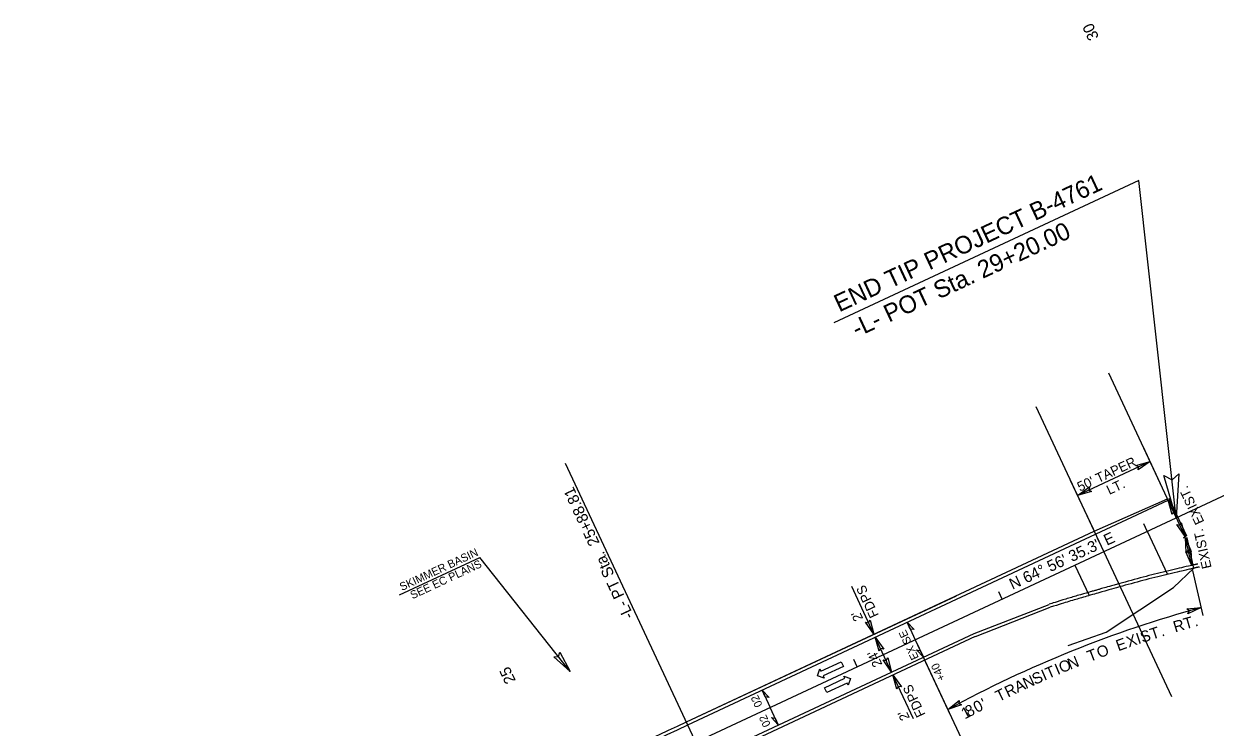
# Model space of a CAD drawing. Extents: x 2320644 to 2322941, y 921672 to 923041.
# Drawn here: x 2321799 to 2322543, y 922465 to 922904 of the extents above; entities that cross this region are included whole.
import ezdxf

# ---------------------------------------------------------------- set-up
doc = ezdxf.new("R2010")
doc.units = 0
for name, color, linetype in [('Matchline', 7, 'Continuous'), ('Matchline Text', 7, 'Continuous'), ('Prop Approach Slab', 7, 'Continuous'), ('Prop Conc Shoulder Berm Gutter', 7, 'Continuous'), ('Prop Dimension', 7, 'Continuous'), ('Prop Horizontal Alignment Station Label', 7, 'Continuous'), ('Prop Horizontal Alignment Tick Small', 7, 'Continuous'), ('Prop Lane Arrow CELL', 7, 'Continuous'), ('Prop North Arrow NAD83 for Plan Sheets CELL', 7, 'Continuous'), ('Prop Superelevation  Arrow CELL', 7, 'Continuous'), ('Prop Terminator CELL', 7, 'Continuous'), ('Sheet Profile Grid Minor CELL', 7, 'Continuous'), ('Sheet Sticker Exception Certification CELL', 7, 'Continuous'), ('Skimmer Basin Both CELL', 7, 'Continuous')]:
    doc.layers.add(name, color=color, linetype=linetype)

msp = doc.modelspace()

# ---------------------------------------------------------------- linework, layer by layer
at = {"layer": 'Matchline'}
msp.add_line((2322219.06, 922455.24), (2322939.2, 922791.92), dxfattribs=at)
at = {"layer": 'Prop Approach Slab'}
for p, q in [((2322213.98, 922466.11), (2322514, 922606.38)), ((2322392.84, 922523.24), (2322439.66, 922541.38)), ((2322224.14, 922444.37), (2322392.84, 922523.24))]:
    msp.add_line(p, q, dxfattribs=at)
msp.add_arc((2152812.15, 1284810.45), 399988, 294.9912984, 295.0568478, dxfattribs=at)
for points, degree in [([(2322528.68, 922565.7), (2322527.14, 922565.35), (2322525.6, 922565), (2322510.52, 922561.51), (2322497.08, 922558.05), (2322480.35, 922553.43), (2322476.17, 922552.25), (2322472, 922551.06), (2322470.33, 922550.58), (2322469.49, 922550.34), (2322466.99, 922549.62), (2322465.32, 922549.14), (2322456.98, 922546.73), (2322450.3, 922544.77), (2322442.33, 922542.25), (2322440.99, 922541.82), (2322439.66, 922541.39)], 3), ([(2322532.6, 922566.58), (2322531.3, 922566.29), (2322529.99, 922565.99), (2322528.68, 922565.7)], 2)]:
    msp.add_open_spline(points, degree=degree, dxfattribs=at)
at = {"layer": 'Prop Conc Shoulder Berm Gutter'}
for p, q in [((2322467.86, 922587.01), (2322513.56, 922607.34)), ((2322213.13, 922467.93), (2322467.86, 922587.01)), ((2322213.13, 922467.93), (2322381.8, 922546.78)), ((2322393.57, 922521.38), (2322440.39, 922539.52)), ((2322224.99, 922442.56), (2322393.65, 922521.41))]:
    msp.add_line(p, q, dxfattribs=at)
msp.add_arc((2152812.15, 1284810.45), 399986, 295.0427173, 295.0568478, dxfattribs=at)
for points, degree in [([(2322529.12, 922563.74), (2322528.97, 922563.71), (2322528.83, 922563.68), (2322525.7, 922562.97), (2322522.72, 922562.28), (2322516.78, 922560.87), (2322501.94, 922557.27), (2322487.21, 922553.31), (2322472.51, 922549.13), (2322469.57, 922548.28), (2322463.69, 922546.59), (2322460.75, 922545.74), (2322451.98, 922543.16), (2322446.16, 922541.4), (2322440.39, 922539.52)], 3), ([(2322533.47, 922564.72), (2322532.02, 922564.4), (2322530.57, 922564.07), (2322529.12, 922563.74)], 2)]:
    msp.add_open_spline(points, degree=degree, dxfattribs=at)
at = {"layer": 'Prop Dimension'}
msp.add_line((2322218.43, 922456.6), (2322137.68, 922629.33), dxfattribs=at)
at = {"layer": 'Prop Horizontal Alignment Station Label'}
for p, q in [((2322350.95, 922530.15), (2322356.02, 922519.27)), ((2322260.36, 922487.8), (2322265.43, 922476.92))]:
    msp.add_line(p, q, dxfattribs=at)
for points in [[(2322350.95, 922530.15), (2322355.3, 922525.56), (2322352.9, 922525.96)], [(2322361.1, 922508.4), (2322356.75, 922512.99), (2322359.15, 922512.59)], [(2322260.36, 922487.8), (2322264.71, 922483.2), (2322262.31, 922483.6)], [(2322270.51, 922466.05), (2322266.16, 922470.64), (2322268.56, 922470.24)]]:
    msp.add_lwpolyline(points, close=True, dxfattribs=at)
at = {"layer": 'Prop Horizontal Alignment Tick Small'}
for p, q in [((2322500.96, 922587.04), (2322498.84, 922591.57)), ((2322410.37, 922544.68), (2322408.26, 922549.21)), ((2322319.78, 922502.33), (2322317.67, 922506.86))]:
    msp.add_line(p, q, dxfattribs=at)
at = {"layer": 'Prop Lane Arrow CELL'}
for p, q in [((2322294.96, 922496.75), (2322296.46, 922500.99)), ((2322296.46, 922500.99), (2322297.09, 922499.63)), ((2322297.09, 922499.63), (2322309.78, 922505.54)), ((2322311.18, 922502.55), (2322298.49, 922496.64)), ((2322309.78, 922505.54), (2322311.18, 922502.55)), ((2322299.12, 922495.28), (2322294.96, 922496.75)), ((2322298.49, 922496.64), (2322299.12, 922495.28)), ((2322299.37, 922489.26), (2322312.06, 922495.18)), ((2322312.06, 922495.18), (2322311.43, 922496.54)), ((2322311.43, 922496.54), (2322315.59, 922495.06)), ((2322315.59, 922495.06), (2322314.09, 922490.83)), ((2322300.77, 922486.27), (2322299.37, 922489.26)), ((2322313.46, 922492.19), (2322300.77, 922486.27)), ((2322314.09, 922490.83), (2322313.46, 922492.19))]:
    msp.add_line(p, q, dxfattribs=at)
at = {"layer": 'Prop North Arrow NAD83 for Plan Sheets CELL'}
for p, q in [((2322495.73, 922806.14), (2322305.22, 922717.23)), ((2322519.08, 922595.51), (2322495.73, 922806.14)), ((2322513.17, 922608.16), (2322498.37, 922639.89)), ((2322502.69, 922630.61), (2322457.38, 922609.47)), ((2322467.27, 922588.26), (2322453.05, 922618.74)), ((2322524.6, 922583.69), (2322514, 922606.38)), ((2322523.48, 922583.16), (2322525.43, 922584.08)), ((2322525.77, 922583.02), (2322523.7, 922582.7)), ((2322528.68, 922565.7), (2322524.79, 922582.87)), ((2322033.95, 922547.27), (2322084.15, 922570.67)), ((2322140.55, 922499.39), (2322084.15, 922570.67)), ((2322535.77, 922534.39), (2322529.38, 922562.59)), ((2322330.24, 922522.67), (2322316.34, 922552.45)), ((2322341.23, 922499.11), (2322331.08, 922520.86)), ((2322356.02, 922519.27), (2322361.1, 922508.4)), ((2322378.24, 922471.65), (2322362.63, 922505.1)), ((2322354.9, 922469.82), (2322342.08, 922497.3))]:
    msp.add_line(p, q, dxfattribs=at)
msp.add_arc((2322726.81, 921833.68), 731.37, 105.23298, 118.62896, dxfattribs=at)
at = {"layer": 'Prop Superelevation  Arrow CELL'}
msp.add_line((2322270.51, 922466.05), (2322265.43, 922476.92), dxfattribs=at)
at = {"layer": 'Sheet Profile Grid Minor CELL'}
for p, q in [((2322514.38, 922607.72), (2322525.43, 922584.08)), ((2322500.96, 922587.04), (2322513.56, 922560.09)), ((2322529.96, 922563.93), (2322525.77, 922583.02)), ((2322455.67, 922565.86), (2322464.56, 922546.84)), ((2322517.38, 922551.92), (2322529.96, 922563.93)), ((2322475.25, 922523.97), (2322517.38, 922551.92)), ((2322451.56, 922515.63), (2322475.25, 922523.97))]:
    msp.add_line(p, q, dxfattribs=at)
at = {"layer": 'Sheet Sticker Exception Certification CELL'}
for points in [[(2322493.88, 922628.21), (2322502.69, 922630.61), (2322495.17, 922625.34), (2322495.54, 922627.27)], [(2322520.73, 922622.85), (2322519.08, 922595.51), (2322511.32, 922621.96), (2322516.47, 922619.06)], [(2322466.19, 922611.87), (2322457.38, 922609.47), (2322464.9, 922614.74), (2322464.54, 922612.81)], [(2322516.4, 922597.57), (2322514, 922606.38), (2322519.28, 922598.86), (2322517.34, 922599.22)], [(2322522.2, 922592.5), (2322524.6, 922583.69), (2322519.32, 922591.21), (2322521.26, 922590.85)], [(2322525.27, 922573.75), (2322524.79, 922582.87), (2322528.35, 922574.4), (2322526.53, 922575.17)], [(2322528.2, 922574.82), (2322528.68, 922565.7), (2322525.12, 922574.17), (2322526.93, 922573.4)], [(2322525.55, 922538.49), (2322534.64, 922539.36), (2322526.33, 922535.44), (2322527.02, 922537.29)], [(2322327.84, 922531.49), (2322330.24, 922522.67), (2322324.96, 922530.2), (2322326.9, 922529.83)], [(2322333.49, 922512.05), (2322331.08, 922520.86), (2322336.36, 922513.34), (2322334.42, 922513.7)], [(2322133.99, 922511.42), (2322140.55, 922499.39), (2322130.24, 922508.55), (2322133.19, 922508.69)], [(2322338.83, 922507.92), (2322341.23, 922499.11), (2322335.96, 922506.64), (2322337.89, 922506.27)], [(2322344.48, 922488.49), (2322342.08, 922497.3), (2322347.36, 922489.78), (2322345.42, 922490.14)], [(2322385.02, 922478.59), (2322376.38, 922475.64), (2322383.56, 922481.38), (2322383.31, 922479.43)]]:
    msp.add_lwpolyline(points, close=True, dxfattribs=at)
at = {"layer": 'Skimmer Basin Both CELL'}
for p, q in [((2322476.73, 922686.1), (2322519.08, 922595.51)), ((2322431.43, 922664.92), (2322516.14, 922483.74)), ((2322356.02, 922519.27), (2322398.37, 922428.68))]:
    msp.add_line(p, q, dxfattribs=at)

# ---------------------------------------------------------------- texts
at = {"layer": 'Matchline Text'}
msp.add_text('N 64%%d 56\' 35.3" E', height=7, rotation=24.9913, dxfattribs=at).set_placement((2322416.76, 922550.44))
at = {"layer": 'Prop Dimension'}
msp.add_text('-L- PT Sta.  25+88.81', height=7, rotation=115.05685, dxfattribs=at).set_placement((2322180.43, 922534.08))
at = {"layer": 'Prop North Arrow NAD83 for Plan Sheets CELL'}
for s, height, rotation, p in [('END TIP PROJECT B-4761', 11, 25.01869, (2322308.57, 922723.74)), ('-L- POT Sta. 29+20.00', 11, 25.01869, (2322319.58, 922707.99)), ("50' TAPER", 6, 25.01869, (2322458.9, 922611.67)), ('LT.', 6, 25.01869, (2322477.21, 922609.7)), ('EXIST.', 6, 115.05685, (2322536.66, 922592.94)), ('EXIST.', 6, 102.76135, (2322541.16, 922564.33)), ('SKIMMER BASIN', 5, 24.9913, (2322035.42, 922549.68)), ('SEE EC PLANS', 5, 24.9913, (2322042.04, 922544.49)), ('FDPS', 6, 115.01869, (2322333.44, 922534.6)), (" 2'", 6, 115.01869, (2322324.58, 922530.46)), ('R', 7, 16.69976, (2322518.34, 922523.76)), ('T', 7, 16.17041, (2322524.72, 922525.65)), ('I', 7, 18.62139, (2322495.32, 922516.38)), ('S', 7, 18.40447, (2322497.9, 922517.25)), ('T', 7, 17.90135, (2322503.92, 922519.23)), ('.', 7, 15.66728, (2322530.81, 922527.4)), ('O', 7, 20.68212, (2322470.92, 922507.61)), ('E', 7, 19.67123, (2322482.85, 922512.02)), ('X', 7, 19.12452, (2322489.33, 922514.32)), ('.', 7, 17.39822, (2322509.94, 922521.17)), ("24'", 6, 115.01869, (2322335.61, 922503.83)), ('N', 7, 22.23084, (2322452.8, 922500.45)), ('T', 7, 21.18524, (2322465.01, 922505.34)), ('T', 7, 23.41077, (2322439.13, 922494.67)), ('I', 7, 22.90764, (2322444.94, 922497.17)), ('O', 7, 22.69072, (2322447.45, 922498.23)), ('A', 7, 25.08527, (2322419.93, 922485.98)), ('N', 7, 24.6254, (2322425.18, 922488.42)), ('S', 7, 24.13081, (2322430.84, 922491)), ('I', 7, 23.62769, (2322436.63, 922493.57)), ('FDPS', 6, 115.01869, (2322362.57, 922472.53)), ('T', 7, 26.11775, (2322408.23, 922480.34)), ('R', 7, 25.61463, (2322413.92, 922483.12)), ('8', 7, 27.79663, (2322389.42, 922470.73)), ('0', 7, 27.33675, (2322394.54, 922473.42)), ("'", 7, 26.87688, (2322399.69, 922476.07)), (" 2'", 6, 115.01869, (2322353.71, 922468.39)), ('1', 7, 28.01355, (2322387.01, 922469.45))]:
    msp.add_text(s, height=height, rotation=rotation, dxfattribs=at).set_placement(p)
at = {"layer": 'Prop Superelevation  Arrow CELL'}
for s, p in [('EX SE', (2322358.37, 922508.05)), ('+40', (2322375, 922494.96)), ('02', (2322260.79, 922478.47)), ('02', (2322265.91, 922466.13))]:
    msp.add_text(s, height=5, rotation=115.01869, dxfattribs=at).set_placement(p)
at = {"layer": 'Prop Terminator CELL'}
for s, rotation, p in [('30', 115.05685, (2322470.92, 922895.68)), ('25', 115.04413, (2322106.73, 922493.67))]:
    msp.add_text(s, height=7, rotation=rotation, dxfattribs=at).set_placement(p)

doc.saveas('drawing.dxf')
